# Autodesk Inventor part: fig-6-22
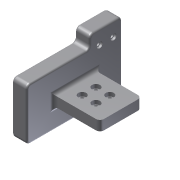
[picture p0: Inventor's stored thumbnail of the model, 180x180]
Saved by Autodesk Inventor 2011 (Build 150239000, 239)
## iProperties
Created: 2004-05
Part Number: fig-6-22
Document SubType Name: Modeling
Designer: CADCIM Technologies
Manufacturer: Standard
Standards Organization: Custom
Density: 1 g/cm^3
Author: CADCIM Technologies
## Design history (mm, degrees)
node "Sketch1"
sketch "Sketch2"
  geometry: L1 (0, 0)-(0, 26.557); L2 (0, 26.557)-(31.986, 26.557); L3 (31.986, 26.557)-(31.986, 32.916); L4 (31.986, 32.916)-(48.42, 32.916); L5 (48.42, 32.916)-(48.42, 0); L6 (48.42, 0)-(0, 0)
  constraints: 12 end point, 4 parallel, 1 perpendicular, 1 vertical
extrude "Extrusion1" new body sketch "Sketch2" distance "d0" = 7.5; taper "d1" = 0 deg
workplane "Work Plane1"
sketch "Sketch3"
  geometry: L1 (7.5, 35.088)-(30.78, 35.088); L2 (30.78, 35.088)-(30.78, 13.871); L3 (30.78, 13.871)-(7.5, 13.871); L4 (7.5, 31.986)-(7.5, 48.42) reference; L5 (7.5, 0)-(7.5, 31.986) reference
  constraints: 6 end point, 2 point on line, 1 horizontal, 1 parallel, 1 perpendicular
extrude "Extrusion2" join sketch "Sketch3" distance "d3" = 5; taper "d4" = 0 deg
fillet "Fillet2" dims "d7" = 2
fillet "Fillet3" dims "d8" = 2
hole "Hole1" diameter "d11" = 3; stored, may be unused: countersink angle "d15" = 90 deg, drill point angle "d17" = 118 deg; dims "d9" = 7, "d10" = 16, "d12" = 6, "d13" = 4, "d14" = 2, "d16" = 8
pattern_linear "Rectangular Pattern1" dims "d20" = 7, "d23" = 7
hole "Hole2" diameter "d26" = 2; stored, may be unused: countersink angle "d30" = 90 deg, drill point angle "d32" = 118 deg; dims "d24" = 5, "d25" = 7, "d27" = 6, "d28" = 3, "d29" = 1, "d31" = 8
pattern_linear "Rectangular Pattern2" dims "d35" = 7
fillet "Fillet4" dims "d36" = 2
fillet "Fillet5" dims "d37" = 1
fillet "Fillet6" dims "d38" = 1
body "Solid1"
other parameters: "d2" = -11
